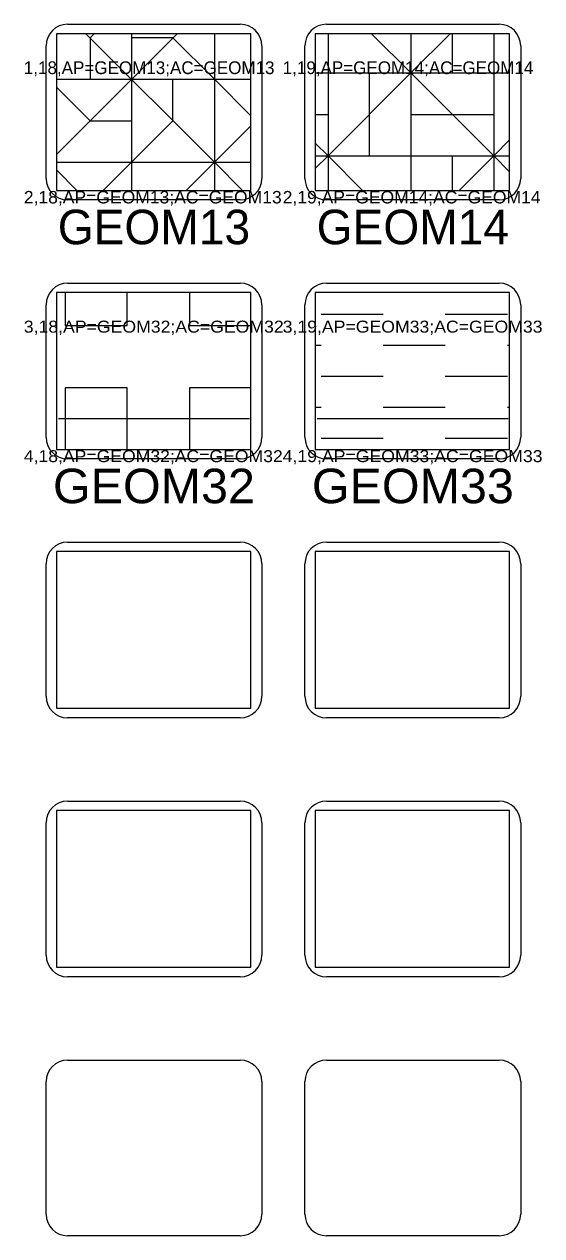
# Model space of a CAD drawing. Extents: x 95935 to 95946.4, y 95971.2 to 95974.7.
# Drawn here: x 95945.235 to 95946.435, y 95971.925 to 95974.732 of the extents above; entities that cross this region are included whole.
import ezdxf
from ezdxf.enums import TextEntityAlignment as Align

# ---------------------------------------------------------------- set-up
doc = ezdxf.new("R2010")
doc.units = 0
doc.header["$LTSCALE"] = 0.032
for name, color, linetype, lineweight in [('1', 7, 'Continuous', 13), ('2', 7, 'Continuous', 13), ('25', 7, 'Continuous', 13), ('6', 7, 'Continuous', 13), ('63', 7, 'Continuous', 13)]:
    doc.layers.add(name, color=color, linetype=linetype, lineweight=lineweight)
doc.layers.add('20', color=7, linetype='Continuous')

msp = doc.modelspace()

# ---------------------------------------------------------------- linework, layer by layer
at = {"layer": '1'}
for p, q in [((95945.3357, 95974.7318), (95945.7357, 95974.7318)), ((95945.9357, 95974.7318), (95946.3357, 95974.7318)), ((95945.2857, 95974.3747), (95945.2857, 95974.6818)), ((95945.7857, 95974.6818), (95945.7857, 95974.3747)), ((95945.8857, 95974.3747), (95945.8857, 95974.6818)), ((95946.3857, 95974.6818), (95946.3857, 95974.3747)), ((95945.7357, 95974.3247), (95945.3357, 95974.3247)), ((95946.3357, 95974.3247), (95945.9357, 95974.3247)), ((95945.3357, 95974.1318), (95945.7357, 95974.1318)), ((95945.9357, 95974.1318), (95946.3357, 95974.1318)), ((95945.2857, 95973.7747), (95945.2857, 95974.0818)), ((95945.7857, 95974.0818), (95945.7857, 95973.7747)), ((95945.8857, 95973.7747), (95945.8857, 95974.0818)), ((95946.3857, 95974.0818), (95946.3857, 95973.7747)), ((95945.7357, 95973.7247), (95945.3357, 95973.7247)), ((95946.3357, 95973.7247), (95945.9357, 95973.7247)), ((95945.3357, 95973.5318), (95945.7357, 95973.5318)), ((95945.9357, 95973.5318), (95946.3357, 95973.5318)), ((95945.2857, 95973.1747), (95945.2857, 95973.4818)), ((95945.7857, 95973.4818), (95945.7857, 95973.1747)), ((95945.8857, 95973.1747), (95945.8857, 95973.4818)), ((95946.3857, 95973.4818), (95946.3857, 95973.1747)), ((95945.7357, 95973.1247), (95945.3357, 95973.1247)), ((95946.3357, 95973.1247), (95945.9357, 95973.1247)), ((95945.3357, 95972.9318), (95945.7357, 95972.9318)), ((95945.9357, 95972.9318), (95946.3357, 95972.9318)), ((95945.2857, 95972.5747), (95945.2857, 95972.8818)), ((95945.7857, 95972.8818), (95945.7857, 95972.5747)), ((95945.8857, 95972.5747), (95945.8857, 95972.8818)), ((95946.3857, 95972.8818), (95946.3857, 95972.5747)), ((95945.7357, 95972.5247), (95945.3357, 95972.5247)), ((95946.3357, 95972.5247), (95945.9357, 95972.5247)), ((95945.3357, 95972.3318), (95945.7357, 95972.3318)), ((95945.9357, 95972.3318), (95946.3357, 95972.3318)), ((95945.2857, 95971.9747), (95945.2857, 95972.2818)), ((95945.7857, 95972.2818), (95945.7857, 95971.9747)), ((95945.8857, 95971.9747), (95945.8857, 95972.2818)), ((95946.3857, 95972.2818), (95946.3857, 95971.9747)), ((95945.7357, 95971.9247), (95945.3357, 95971.9247)), ((95946.3357, 95971.9247), (95945.9357, 95971.9247))]:
    msp.add_line(p, q, dxfattribs=at)
for centre, start, end in [((95945.3357, 95974.6818), 90, 180), ((95945.7357, 95974.6818), 0, 90), ((95945.9357, 95974.6818), 90, 180), ((95946.3357, 95974.6818), 0, 90), ((95945.3357, 95974.3747), 180, 270), ((95945.7357, 95974.3747), 270, 0), ((95945.9357, 95974.3747), 180, 270), ((95946.3357, 95974.3747), 270, 0), ((95945.3357, 95974.0818), 90, 180), ((95945.7357, 95974.0818), 0, 90), ((95945.9357, 95974.0818), 90, 180), ((95946.3357, 95974.0818), 0, 90), ((95945.3357, 95973.7747), 180, 270), ((95945.7357, 95973.7747), 270, 0), ((95945.9357, 95973.7747), 180, 270), ((95946.3357, 95973.7747), 270, 0), ((95945.3357, 95973.4818), 90, 180), ((95945.7357, 95973.4818), 0, 90), ((95945.9357, 95973.4818), 90, 180), ((95946.3357, 95973.4818), 0, 90), ((95945.3357, 95973.1747), 180, 270), ((95945.7357, 95973.1747), 270, 0), ((95945.9357, 95973.1747), 180, 270), ((95946.3357, 95973.1747), 270, 0), ((95945.3357, 95972.8818), 90, 180), ((95945.7357, 95972.8818), 0, 90), ((95945.9357, 95972.8818), 90, 180), ((95946.3357, 95972.8818), 0, 90), ((95945.3357, 95972.5747), 180, 270), ((95945.7357, 95972.5747), 270, 0), ((95945.9357, 95972.5747), 180, 270), ((95946.3357, 95972.5747), 270, 0), ((95945.3357, 95972.2818), 90, 180), ((95945.7357, 95972.2818), 0, 90), ((95945.9357, 95972.2818), 90, 180), ((95946.3357, 95972.2818), 0, 90), ((95945.3357, 95971.9747), 180, 270), ((95945.7357, 95971.9747), 270, 0), ((95945.9357, 95971.9747), 180, 270), ((95946.3357, 95971.9747), 270, 0)]:
    msp.add_arc(centre, 0.05, start, end, dxfattribs=at)
at = {"layer": '2'}
for points in [[(95945.7601, 95974.7099), (95945.3097, 95974.7099), (95945.3097, 95974.3468), (95945.7601, 95974.3468)], [(95946.3601, 95974.7099), (95945.9097, 95974.7099), (95945.9097, 95974.3468), (95946.3601, 95974.3468)], [(95945.7601, 95974.1099), (95945.3097, 95974.1099), (95945.3097, 95973.7468), (95945.7601, 95973.7468)], [(95946.3601, 95974.1099), (95945.9097, 95974.1099), (95945.9097, 95973.7468), (95946.3601, 95973.7468)], [(95945.7601, 95973.5099), (95945.3097, 95973.5099), (95945.3097, 95973.1468), (95945.7601, 95973.1468)], [(95946.3601, 95973.5099), (95945.9097, 95973.5099), (95945.9097, 95973.1468), (95946.3601, 95973.1468)], [(95945.7601, 95972.9099), (95945.3097, 95972.9099), (95945.3097, 95972.5468), (95945.7601, 95972.5468)], [(95946.3601, 95972.9099), (95945.9097, 95972.9099), (95945.9097, 95972.5468), (95946.3601, 95972.5468)]]:
    msp.add_lwpolyline(points, close=True, dxfattribs=at)
at = {"layer": '25'}
for p, q in [((95945.7569, 95973.8178), (95945.3141, 95973.8178)), ((95946.3569, 95973.8178), (95945.9141, 95973.8178))]:
    msp.add_line(p, q, dxfattribs=at)
at = {"layer": '6'}
for p, q in [((95945.5893, 95974.7099), (95945.3097, 95974.4303)), ((95945.6757, 95974.4123), (95945.3781, 95974.7099)), ((95945.3973, 95974.7099), (95945.3877, 95974.7003)), ((95945.3877, 95974.7003), (95945.3877, 95974.6043)), ((95945.4837, 95974.7099), (95945.4837, 95974.3468)), ((95945.6757, 95974.7099), (95945.6757, 95974.3468)), ((95945.9392, 95974.7099), (95945.9392, 95974.3468)), ((95946.1312, 95974.619), (95946.0403, 95974.7099)), ((95946.1312, 95974.7099), (95946.1312, 95974.3468)), ((95946.2221, 95974.7099), (95946.1312, 95974.619)), ((95946.2272, 95974.7099), (95946.2272, 95974.619)), ((95946.3232, 95974.7099), (95946.3232, 95974.3468)), ((95945.9097, 95974.619), (95946.3601, 95974.619)), ((95945.9392, 95974.427), (95946.1312, 95974.619)), ((95946.0352, 95974.427), (95946.0352, 95974.619)), ((95946.1312, 95974.619), (95946.3232, 95974.427)), ((95945.3097, 95974.6043), (95945.7601, 95974.6043)), ((95945.3097, 95974.5863), (95945.3877, 95974.5083)), ((95945.6757, 95974.6043), (95945.7601, 95974.5199)), ((95945.3877, 95974.5083), (95945.4837, 95974.5083)), ((95945.7601, 95974.4967), (95945.6757, 95974.4123)), ((95945.9097, 95974.523), (95945.9392, 95974.523)), ((95946.1312, 95974.523), (95946.3232, 95974.523)), ((95945.9097, 95974.4565), (95945.9392, 95974.427)), ((95946.3232, 95974.427), (95946.3601, 95974.4639)), ((95945.3097, 95974.4123), (95945.7601, 95974.4123)), ((95945.4837, 95974.4123), (95945.4182, 95974.3468)), ((95945.6757, 95974.4123), (95945.6102, 95974.3468)), ((95945.7412, 95974.3468), (95945.6757, 95974.4123)), ((95945.9097, 95974.427), (95946.3601, 95974.427)), ((95945.9392, 95974.427), (95945.9097, 95974.3975)), ((95946.0194, 95974.3468), (95945.9392, 95974.427)), ((95946.2272, 95974.427), (95946.2272, 95974.3468)), ((95946.3232, 95974.427), (95946.243, 95974.3468)), ((95946.3601, 95974.3901), (95946.3232, 95974.427)), ((95945.3572, 95974.3468), (95945.3097, 95974.3943)), ((95945.3299, 95974.1099), (95945.3299, 95974.0334)), ((95945.6179, 95974.1099), (95945.6179, 95974.0334)), ((95946.067, 95974.0596), (95945.923, 95974.0596)), ((95946.355, 95974.0596), (95946.211, 95974.0596)), ((95945.6179, 95974.0334), (95945.7601, 95974.0334)), ((95945.923, 95973.9876), (95945.9097, 95973.9876)), ((95946.211, 95973.9876), (95946.067, 95973.9876)), ((95946.3601, 95973.9876), (95946.355, 95973.9876)), ((95946.067, 95973.9156), (95945.923, 95973.9156)), ((95946.355, 95973.9156), (95946.211, 95973.9156)), ((95945.923, 95973.8436), (95945.9097, 95973.8436)), ((95946.211, 95973.8436), (95946.067, 95973.8436)), ((95946.3601, 95973.8436), (95946.355, 95973.8436)), ((95946.067, 95973.7716), (95945.923, 95973.7716)), ((95946.355, 95973.7716), (95946.211, 95973.7716))]:
    msp.add_line(p, q, dxfattribs=at)
for points in [[(95945.6757, 95974.6043), (95945.5797, 95974.7003), (95945.4837, 95974.7003)], [(95945.4837, 95974.4123), (95945.5797, 95974.5083), (95945.5797, 95974.6043)], [(95945.3299, 95974.0334), (95945.4739, 95974.0334), (95945.4739, 95974.1099)], [(95945.4739, 95973.7468), (95945.4739, 95973.8894), (95945.3299, 95973.8894), (95945.3299, 95973.7468)], [(95945.7601, 95973.8894), (95945.6179, 95973.8894), (95945.6179, 95973.7468)]]:
    msp.add_lwpolyline(points, dxfattribs=at)

# ---------------------------------------------------------------- texts
at = {"layer": '20'}
for s, p in [('GEOM13', (95945.5357, 95974.222)), ('GEOM14', (95946.1358, 95974.222))]:
    msp.add_text(s, height=0.08, dxfattribs=at).set_placement(p, align=Align.CENTER)
at = {"layer": '20', "width": 1.05}
for s, p in [('GEOM32', (95945.5357, 95973.622)), ('GEOM33', (95946.1358, 95973.622))]:
    msp.add_text(s, height=0.08, dxfattribs=at).set_placement(p, align=Align.CENTER)
at = {"layer": '63'}
for s, p in [('1,18,AP=GEOM13;AC=GEOM13', (95945.2341, 95974.6163)), ('1,19,AP=GEOM14;AC=GEOM14', (95945.8341, 95974.6163))]:
    msp.add_text(s, height=0.0295, dxfattribs=at).set_placement(p)
for s, height, width, p in [('2,18,AP=GEOM13;AC=GEOM13', 0.0289, 1.05, (95945.2341, 95974.3166)), ('2,19,AP=GEOM14;AC=GEOM14', 0.0289, 1.05, (95945.8341, 95974.3166)), ('3,18,AP=GEOM32;AC=GEOM32', 0.0278, 1.1, (95945.2341, 95974.0172)), ('3,19,AP=GEOM33;AC=GEOM33', 0.0278, 1.1, (95945.8341, 95974.0172)), ('4,18,AP=GEOM32;AC=GEOM32', 0.0277, 1.1, (95945.2341, 95973.7172)), ('4,19,AP=GEOM33;AC=GEOM33', 0.0278, 1.1, (95945.8341, 95973.7172))]:
    msp.add_text(s, height=height, dxfattribs=dict(at, width=width)).set_placement(p)

doc.saveas('drawing.dxf')
